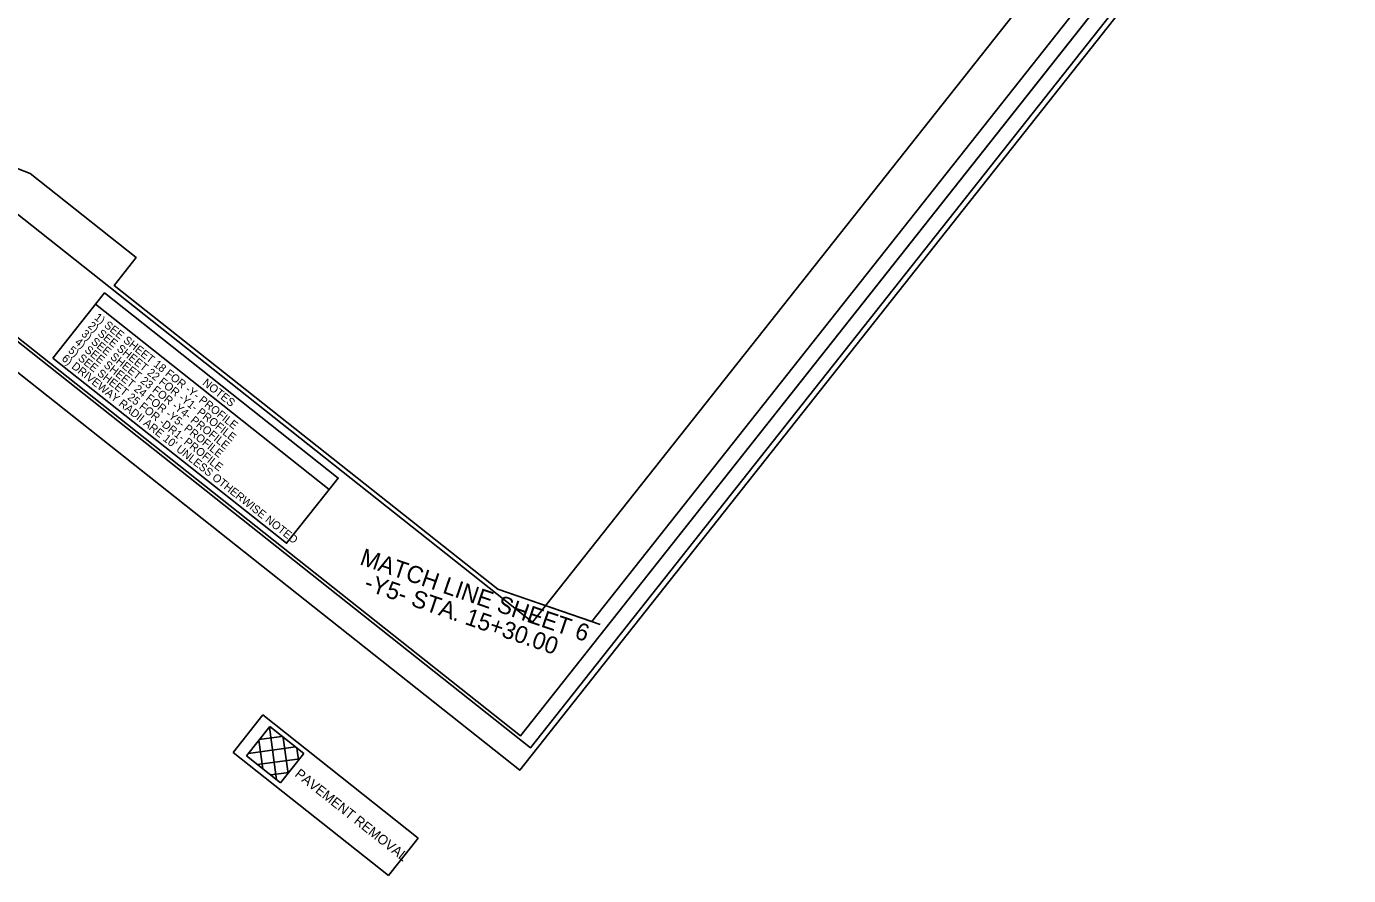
# Model space of a CAD drawing. Extents: x 1781865 to 1783979, y 813086 to 815120.
# Drawn here: x 1782780 to 1783864, y 813086 to 813782 of the extents above; entities that cross this region are included whole.
import ezdxf

# ---------------------------------------------------------------- set-up
doc = ezdxf.new("R2010")
doc.units = 0
for name, color, linetype in [('Matchline', 7, 'Continuous'), ('Matchline Text', 7, 'Continuous'), ('Prop DSN Text', 7, 'Continuous'), ('Prop Grid Mask', 7, 'Continuous'), ('Prop Rem of Exist Asph Pvmt', 7, 'Continuous'), ('Sheet Clip Boundary CELL', 7, 'Continuous'), ('Sheet Cutting Line CELL', 7, 'Continuous'), ('Sheet Layout Plan Border', 7, 'Continuous'), ('Sheet Plan CELL', 7, 'Continuous'), ('Sheet Plan Layout CELL', 7, 'Continuous'), ('Sheet Plot Border Inside CELL', 7, 'Continuous'), ('Sheet Plot Border Outside CELL', 7, 'Continuous')]:
    doc.layers.add(name, color=color, linetype=linetype)

msp = doc.modelspace()

# ---------------------------------------------------------------- linework, layer by layer
at = {"layer": 'Matchline'}
for p, q in [((1782783.1, 813661.2), (1782497.5, 813772.1)), ((1782783.1, 813661.2), (1782870.1, 813592.2)), ((1782870.1, 813592.2), (1782852, 813569.4)), ((1782852, 813569.4), (1783166.6, 813320.4)), ((1783166.6, 813320.4), (1783250.7, 813291.6))]:
    msp.add_line(p, q, dxfattribs=at)
at = {"layer": 'Prop Grid Mask'}
for p, q in [((1782973.9, 813217.5), (1782949.6, 813186.8)), ((1783101.4, 813116.6), (1782973.9, 813217.5)), ((1782949.6, 813186.8), (1783077, 813085.9)), ((1783077, 813085.9), (1783101.4, 813116.6))]:
    msp.add_line(p, q, dxfattribs=at)
for points in [[(1782801.9, 813509.8), (1782993.5, 813358.1), (1783035.8, 813411.5), (1782844.2, 813563.2)], [(1782836.7, 813553.9), (1783028.4, 813402.2), (1783035.8, 813411.5), (1782844.2, 813563.2)]]:
    msp.add_lwpolyline(points, close=True, dxfattribs=at)
at = {"layer": 'Prop Rem of Exist Asph Pvmt'}
for p, q in [((1782960.6, 813184), (1782979.7, 813208.1)), ((1782979.4, 813207.4), (1782985.3, 813164.4)), ((1782979.7, 813208.1), (1783007.6, 813185.9)), ((1782970.7, 813196.8), (1782974, 813173.4)), ((1782971.1, 813197.2), (1782989.4, 813199.8)), ((1782990.7, 813198.8), (1782994.7, 813169.6)), ((1782988.6, 813161.9), (1782960.6, 813184)), ((1782962.1, 813185.9), (1783000.7, 813191.2)), ((1783007.6, 813185.9), (1782988.6, 813161.9)), ((1783001.9, 813190.5), (1783003.3, 813180.5)), ((1782969.6, 813176.9), (1783004.2, 813181.6)), ((1782980.5, 813168.3), (1782995.2, 813170.3))]:
    msp.add_line(p, q, dxfattribs=at)
at = {"layer": 'Sheet Clip Boundary CELL'}
msp.add_lwpolyline([(1782552.2, 814707.5), (1782111.4, 814173.2), (1782528.7, 813842.8), (1782497.5, 813772.1), (1782783.1, 813661.2), (1782870.1, 813592.2), (1782852, 813569.4), (1783166.6, 813320.4), (1783243.8, 813293.9), (1783730.1, 813908.2), (1783580.1, 814026.9), (1783674.7, 814147.7), (1783547.9, 814248.1), (1783381.9, 814035.5), (1783080.3, 814276), (1783101.5, 814390.8)], close=True, dxfattribs=at)
at = {"layer": 'Sheet Cutting Line CELL'}
msp.add_line((1781864.7, 814217.1), (1783184.6, 813172.1), dxfattribs=at)
at = {"layer": 'Sheet Layout Plan Border'}
msp.add_lwpolyline([(1782097.5, 814162.5), (1783195.2, 813293.5), (1783715.7, 813950.9), (1783567.3, 814068.4), (1783698.6, 814234.2), (1782749.3, 814985.7)], close=True, dxfattribs=at)
at = {"layer": 'Sheet Plan CELL'}
for points in [[(1783837, 814023.6), (1782660.9, 814954.7), (1782009.2, 814131.4), (1783185.2, 813200.3)], [(1782009.2, 814131.4), (1782660.9, 814954.7), (1783680.1, 814147.8), (1783587, 814030.1), (1783743.8, 813905.9), (1783185.2, 813200.3)]]:
    msp.add_lwpolyline(points, close=True, dxfattribs=at)
at = {"layer": 'Sheet Plan Layout CELL'}
msp.add_lwpolyline([(1782660.9, 814954.7), (1782009.2, 814131.4), (1783185.2, 813200.4), (1783705.7, 813857.8), (1783518.1, 814006.3), (1783649.4, 814172.1)], close=True, dxfattribs=at)
at = {"layer": 'Sheet Plot Border Inside CELL'}
msp.add_lwpolyline([(1781887.3, 814224.7), (1783193.5, 813190.6), (1783848.3, 814017.8), (1782542.1, 815051.9)], close=True, dxfattribs=at)
at = {"layer": 'Sheet Plot Border Outside CELL'}
msp.add_lwpolyline([(1781864.7, 814217.1), (1783184.6, 813172.1), (1783864.3, 814030.7), (1782544.4, 815075.6)], close=True, dxfattribs=at)

# ---------------------------------------------------------------- texts
at = {"layer": 'Matchline Text'}
for s, p in [('MATCH LINE SHEET 6 ', (1783052.7, 813341)), ('-Y5- STA. 15+30.00', (1783056.2, 813320.4))]:
    msp.add_text(s, height=14, rotation=341.0737, dxfattribs=at).set_placement(p)
at = {"layer": 'Prop DSN Text'}
for s, height, p in [('1) SEE SHEET 18 FOR -Y- PROFILE ', 6.56, (1782835.3, 813542.1)), ('3) SEE SHEET 23 FOR -Y4- PROFILE', 6.56, (1782824.6, 813528.6)), ('2) SEE SHEET 22 FOR -Y1- PROFILE', 6.56, (1782830, 813535.3)), ('5) SEE SHEET 25 FOR -DR1- PROFILE', 6.56, (1782813.9, 813515.1)), ('4) SEE SHEET 24 FOR -Y5- PROFILE', 6.56, (1782819.3, 813521.9)), ("6) DRIVEWAY RADII ARE 10' UNLESS OTHERWISE NOTED", 6.56, (1782808.6, 813508.4)), ('NOTES', 6.64, (1782924, 813488.5)), ('PAVEMENT REMOVAL', 8, (1782999.6, 813167.8))]:
    msp.add_text(s, height=height, rotation=321.6309, dxfattribs=at).set_placement(p)

doc.saveas('drawing.dxf')
